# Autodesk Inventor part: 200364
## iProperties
Created: 2007-12
Part Number: 200364
Document SubType Name: Modeling
Designer: TH
Density: 7.85 g/cm^3
Mass: 153.679 g
Surface Area: 267.655 cm^2
Volume: 19.5769 cm^3
Material: Steel
Description: POWER MOUNTING BRACKET
Component Category: Lower Component
Author: TH
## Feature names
1. Extrusion1
2. Fillet1
3. Extrusion2
4. Fillet2
5. Fillet3
6. Shell1
7. Extrusion3
8. Extrusion4
9. Mirror1
10. Fillet4
11. Fillet5
12. Hole1
13. Hole2
14. Hole3
15. Hole4
